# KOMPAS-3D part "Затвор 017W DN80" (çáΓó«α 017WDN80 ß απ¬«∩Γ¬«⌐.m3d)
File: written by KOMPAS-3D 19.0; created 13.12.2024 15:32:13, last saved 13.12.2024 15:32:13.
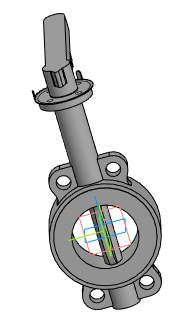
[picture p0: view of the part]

Document properties: Автор: Евгений; Полное имя файла: ..\Затвор 017WDN80.a3d

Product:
- Part/product: Затвор 017W DN80
    Масса: 6.34869

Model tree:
1. Операция без истории:1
